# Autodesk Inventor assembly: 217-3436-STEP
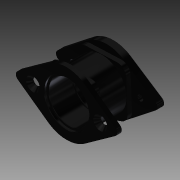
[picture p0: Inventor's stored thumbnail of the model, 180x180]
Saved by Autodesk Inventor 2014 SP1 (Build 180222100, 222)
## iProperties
Created: 2014-06
Part Number: 217-3436-STEP
Document SubType Name: Assembly
Designer: Michael
Title: 217-3436-STEP.STEP
Description: STEP AP214
Creation Date: 2013-12-10
Sending System: SolidWorks 2013
Preprocessor: SwSTEP 2.0
Author: Michael
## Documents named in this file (3)
- C:\Users\Michael\Documents\Inventor\6CIM\Imported Components\217-3436-STEP\217-3436-STEP.iam
- C:\Users\Michael\Documents\Inventor\6CIM\Imported Components\217-3436-STEP\217-3436-001 Rev2.ipt
- C:\Users\Michael\Documents\Inventor\6CIM\Imported Components\217-3436-STEP\217-3436-002 Rev2.ipt
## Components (2 placed, 2 different names)
1. 217-3436-001 Rev2_1 — Mate:1, Mate:2
2. 217-3436-002 Rev2_2 — Mate:1, Mate:2
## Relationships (2: Mate 2)
- Mate:1: 217-3436-001 Rev2_1 ↔ 217-3436-002 Rev2_2
- Mate:2: 217-3436-001 Rev2_1 ↔ 217-3436-002 Rev2_2
